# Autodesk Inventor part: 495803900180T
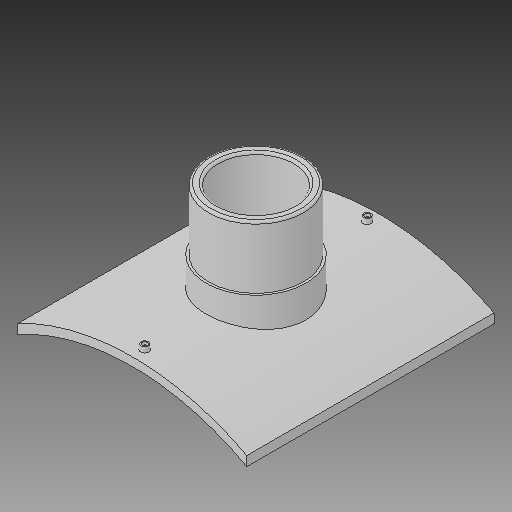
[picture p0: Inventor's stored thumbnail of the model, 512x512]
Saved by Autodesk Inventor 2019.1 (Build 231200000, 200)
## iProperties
Created: 2017-10
Part Number: 495803900180T
Material: Generic
Description: PLASSON BRANCH SADDLE  900x180
Document SubType Name: Modeling
Designer: KIM
Mass: 2754.05 g
Surface Area: 3037.44 cm^2
Volume: 2754.05 cm^3
Density: 1 g/cm^3
Appearance: Default
Author: KIM
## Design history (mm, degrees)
derived "495803.ipt"
feature "Solid1::495803.ipt"
tag "TaggingFeature1"
body "Solid1"
other parameters: "d1" = 16, "d2" = 435, "d4" = 0, "d12" = 475.6, "d13" = 14, "d14" = 211.5, "d16" = 5 deg, "d18" = 4, "d19" = 14, "d20" = 0, "d21" = 3, "d22" = 0, "d23" = 635, "d24" = 189, "d25" = 16, "d26" = 144, "d28" = 0, "d29" = 9.6, "d31" = 0, "d32" = 84.5, "d33" = 0, "d34" = 9, "d37" = 118.3, "d38" = 0, "d39" = 4.5, "B_" = 435, "H_" = 169, "x_" = 16, "D_" = 16
